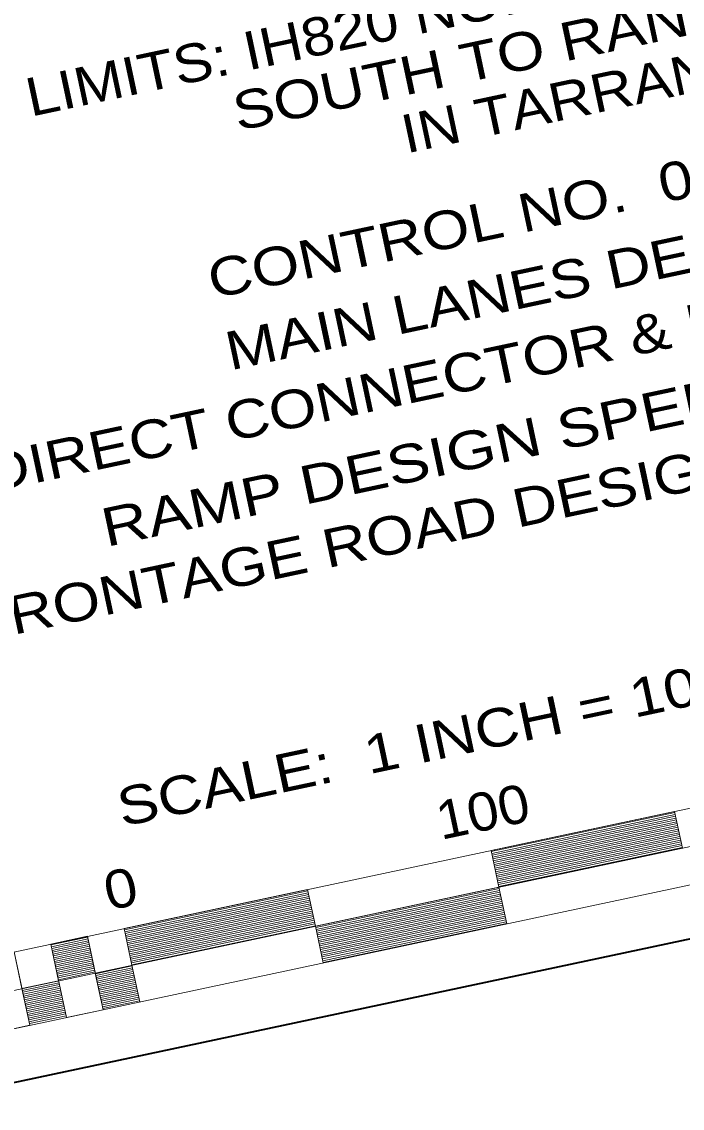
# Model space of a CAD drawing. Extents: x 2357218 to 2371708, y 6973728 to 6980157.
# Drawn here: x 2370630.2 to 2370806.3, y 6976807.8 to 6977097.4 of the extents above; entities that cross this region are included whole.
import ezdxf
from ezdxf.enums import TextEntityAlignment as Align

# ---------------------------------------------------------------- set-up
doc = ezdxf.new("R2010")
doc.units = 0
doc.header["$LTSCALE"] = 2
doc.layers.add('61', color=7, linetype='Continuous')
doc.layers.add('62', color=7, linetype='Continuous', lineweight=13)
doc.layers.add('63', color=7, linetype='Continuous', lineweight=13)

msp = doc.modelspace()

# ---------------------------------------------------------------- linework, layer by layer
at = {"layer": '62', "lineweight": 35}
msp.add_line((2371176.22, 6976931.098), (2370539.396, 6976795.736), dxfattribs=at)
at = {"layer": '62'}
for p, q in [((2370559.68, 6976834.897), (2370950.993, 6976918.073)), ((2370561.761, 6976825.114), (2370953.073, 6976908.29)), ((2370755.398, 6976876.2), (2370804.31, 6976886.597)), ((2370804.251, 6976886.882), (2370806.329, 6976877.099)), ((2370755.502, 6976875.711), (2370804.414, 6976886.108)), ((2370755.606, 6976875.221), (2370804.519, 6976885.619)), ((2370755.709, 6976874.731), (2370804.622, 6976885.129)), ((2370755.813, 6976874.243), (2370804.727, 6976884.64)), ((2370755.917, 6976873.754), (2370804.83, 6976884.151)), ((2370756.021, 6976873.265), (2370804.934, 6976883.661)), ((2370756.125, 6976872.777), (2370805.038, 6976883.173)), ((2370756.229, 6976872.286), (2370805.142, 6976882.683)), ((2370756.334, 6976871.797), (2370805.247, 6976882.194)), ((2370756.437, 6976871.309), (2370805.35, 6976881.705)), ((2370756.54, 6976870.82), (2370805.455, 6976881.216)), ((2370756.644, 6976870.331), (2370805.559, 6976880.727)), ((2370756.748, 6976869.841), (2370805.662, 6976880.238)), ((2370756.853, 6976869.352), (2370805.767, 6976879.749)), ((2370756.957, 6976868.864), (2370805.87, 6976879.26)), ((2370757.06, 6976868.374), (2370805.974, 6976878.77)), ((2370757.165, 6976867.885), (2370806.078, 6976878.281)), ((2370757.268, 6976867.395), (2370806.182, 6976877.792)), ((2370755.336, 6976876.485), (2370757.416, 6976866.702)), ((2370757.373, 6976866.907), (2370806.287, 6976877.303)), ((2370706.422, 6976866.088), (2370708.502, 6976856.304)), ((2370708.583, 6976855.926), (2370757.496, 6976866.323)), ((2370757.416, 6976866.702), (2370759.495, 6976856.919)), ((2370657.583, 6976855.338), (2370706.497, 6976865.736)), ((2370657.687, 6976854.85), (2370706.601, 6976865.247)), ((2370657.791, 6976854.359), (2370706.705, 6976864.756)), ((2370657.896, 6976853.871), (2370706.81, 6976864.267)), ((2370657.999, 6976853.382), (2370706.913, 6976863.778)), ((2370658.103, 6976852.892), (2370707.018, 6976863.288)), ((2370708.686, 6976855.438), (2370757.6, 6976865.834)), ((2370708.789, 6976854.948), (2370757.704, 6976865.344)), ((2370708.893, 6976854.46), (2370757.808, 6976864.856)), ((2370708.997, 6976853.97), (2370757.913, 6976864.367)), ((2370709.101, 6976853.481), (2370758.017, 6976863.877)), ((2370709.205, 6976852.993), (2370758.12, 6976863.39)), ((2370658.207, 6976852.403), (2370707.121, 6976862.8)), ((2370658.311, 6976851.915), (2370707.225, 6976862.31)), ((2370658.416, 6976851.425), (2370707.328, 6976861.822)), ((2370658.52, 6976850.936), (2370707.432, 6976861.333)), ((2370658.623, 6976850.447), (2370707.537, 6976860.843)), ((2370658.728, 6976849.958), (2370707.64, 6976860.354)), ((2370709.31, 6976852.503), (2370758.224, 6976862.9)), ((2370709.414, 6976852.014), (2370758.328, 6976862.412)), ((2370709.517, 6976851.524), (2370758.432, 6976861.923)), ((2370709.622, 6976851.035), (2370758.537, 6976861.433)), ((2370709.725, 6976850.547), (2370758.64, 6976860.944)), ((2370709.829, 6976850.057), (2370758.744, 6976860.454)), ((2370658.832, 6976849.469), (2370707.744, 6976859.864)), ((2370658.935, 6976848.979), (2370707.849, 6976859.377)), ((2370659.039, 6976848.49), (2370707.952, 6976858.887)), ((2370659.143, 6976848.001), (2370708.057, 6976858.397)), ((2370659.247, 6976847.512), (2370708.16, 6976857.909)), ((2370659.351, 6976847.023), (2370708.265, 6976857.421)), ((2370709.933, 6976849.567), (2370758.848, 6976859.965)), ((2370710.037, 6976849.078), (2370758.952, 6976859.476)), ((2370710.141, 6976848.589), (2370759.056, 6976858.986)), ((2370710.245, 6976848.1), (2370759.159, 6976858.498)), ((2370710.35, 6976847.61), (2370759.264, 6976858.008)), ((2370710.454, 6976847.122), (2370759.368, 6976857.519)), ((2370657.509, 6976855.691), (2370659.588, 6976845.908)), ((2370659.456, 6976846.534), (2370708.369, 6976856.931)), ((2370659.559, 6976846.045), (2370708.472, 6976856.443)), ((2370708.502, 6976856.304), (2370710.581, 6976846.522)), ((2370710.558, 6976846.633), (2370759.472, 6976857.03)), ((2370637.943, 6976851.531), (2370640.022, 6976841.749)), ((2370637.985, 6976851.338), (2370647.767, 6976853.419)), ((2370638.088, 6976850.849), (2370647.87, 6976852.929)), ((2370638.192, 6976850.358), (2370647.976, 6976852.439)), ((2370638.296, 6976849.87), (2370648.078, 6976851.95)), ((2370638.401, 6976849.381), (2370648.183, 6976851.461)), ((2370647.726, 6976853.612), (2370649.805, 6976843.829)), ((2370628.16, 6976849.453), (2370630.24, 6976839.67)), ((2370638.505, 6976848.891), (2370648.287, 6976850.971)), ((2370638.608, 6976848.403), (2370648.39, 6976850.482)), ((2370638.711, 6976847.914), (2370648.494, 6976849.993)), ((2370638.815, 6976847.426), (2370648.598, 6976849.505)), ((2370638.92, 6976846.937), (2370648.702, 6976849.015)), ((2370639.024, 6976846.447), (2370648.806, 6976848.526)), ((2370639.127, 6976845.958), (2370648.911, 6976848.036)), ((2370639.232, 6976845.468), (2370649.015, 6976847.548)), ((2370639.336, 6976844.979), (2370649.118, 6976847.057)), ((2370639.44, 6976844.491), (2370649.222, 6976846.569)), ((2370639.543, 6976844.001), (2370649.326, 6976846.08)), ((2370649.846, 6976843.635), (2370659.63, 6976845.714)), ((2370659.588, 6976845.909), (2370661.668, 6976836.125)), ((2370659.588, 6976845.908), (2370661.668, 6976836.126)), ((2370639.647, 6976843.513), (2370649.43, 6976845.59)), ((2370639.751, 6976843.023), (2370649.534, 6976845.102)), ((2370639.855, 6976842.534), (2370649.639, 6976844.613)), ((2370639.96, 6976842.045), (2370649.742, 6976844.124)), ((2370649.805, 6976843.83), (2370651.886, 6976834.047)), ((2370649.805, 6976843.828), (2370651.884, 6976834.046)), ((2370649.951, 6976843.146), (2370659.734, 6976845.224)), ((2370650.054, 6976842.657), (2370659.837, 6976844.737)), ((2370650.158, 6976842.168), (2370659.942, 6976844.248)), ((2370650.262, 6976841.678), (2370660.046, 6976843.758)), ((2370650.366, 6976841.189), (2370660.149, 6976843.27)), ((2370650.471, 6976840.7), (2370660.254, 6976842.78)), ((2370630.241, 6976839.659), (2370640.025, 6976841.739)), ((2370630.346, 6976839.17), (2370640.129, 6976841.249)), ((2370630.449, 6976838.681), (2370640.234, 6976840.761)), ((2370630.554, 6976838.192), (2370640.338, 6976840.271)), ((2370650.574, 6976840.211), (2370660.357, 6976842.291)), ((2370650.678, 6976839.722), (2370660.462, 6976841.802)), ((2370650.782, 6976839.232), (2370660.566, 6976841.313)), ((2370650.885, 6976838.744), (2370660.669, 6976840.824)), ((2370650.989, 6976838.255), (2370660.773, 6976840.334)), ((2370651.093, 6976837.766), (2370660.877, 6976839.846)), ((2370630.239, 6976839.671), (2370632.319, 6976829.887)), ((2370630.24, 6976839.671), (2370632.319, 6976829.888)), ((2370630.657, 6976837.702), (2370640.441, 6976839.782)), ((2370630.762, 6976837.214), (2370640.546, 6976839.293)), ((2370630.866, 6976836.725), (2370640.65, 6976838.804)), ((2370630.969, 6976836.235), (2370640.754, 6976838.315)), ((2370631.073, 6976835.746), (2370640.857, 6976837.826)), ((2370631.177, 6976835.257), (2370640.961, 6976837.337)), ((2370651.197, 6976837.277), (2370660.982, 6976839.357)), ((2370651.302, 6976836.786), (2370661.085, 6976838.866)), ((2370651.405, 6976836.298), (2370661.189, 6976838.378)), ((2370651.51, 6976835.809), (2370661.293, 6976837.888)), ((2370651.613, 6976835.32), (2370661.397, 6976837.399)), ((2370631.282, 6976834.768), (2370641.066, 6976836.848)), ((2370631.386, 6976834.279), (2370641.169, 6976836.358)), ((2370631.489, 6976833.79), (2370641.274, 6976835.87)), ((2370631.594, 6976833.301), (2370641.378, 6976835.38)), ((2370631.698, 6976832.811), (2370641.481, 6976834.89)), ((2370631.802, 6976832.322), (2370641.586, 6976834.401)), ((2370651.717, 6976834.831), (2370661.501, 6976836.911)), ((2370651.821, 6976834.341), (2370661.605, 6976836.421)), ((2370631.906, 6976831.834), (2370641.689, 6976833.912)), ((2370632.009, 6976831.344), (2370641.794, 6976833.423)), ((2370632.113, 6976830.855), (2370641.897, 6976832.934)), ((2370632.217, 6976830.365), (2370642.001, 6976832.445))]:
    msp.add_line(p, q, dxfattribs=at)
for points in [[(2370757.416, 6976866.702), (2370806.329, 6976877.099), (2370804.251, 6976886.882), (2370755.336, 6976876.485)], [(2370659.588, 6976845.908), (2370708.502, 6976856.304), (2370706.422, 6976866.088), (2370657.509, 6976855.691)], [(2370710.581, 6976846.522), (2370759.495, 6976856.919), (2370757.416, 6976866.702), (2370708.502, 6976856.304)], [(2370642.101, 6976831.966), (2370651.884, 6976834.046), (2370647.726, 6976853.612), (2370637.943, 6976851.531)], [(2370622.537, 6976827.807), (2370632.319, 6976829.887), (2370628.16, 6976849.453), (2370618.377, 6976847.373)]]:
    msp.add_lwpolyline(points, close=True, dxfattribs=at)
at = {"layer": '63'}
for p, q in [((2370559.68, 6976834.897), (2370950.993, 6976918.073)), ((2370561.761, 6976825.114), (2370953.073, 6976908.29)), ((2370563.839, 6976815.332), (2370955.152, 6976898.507)), ((2370755.398, 6976876.2), (2370804.31, 6976886.597)), ((2370804.251, 6976886.882), (2370806.329, 6976877.099)), ((2370755.502, 6976875.711), (2370804.414, 6976886.108)), ((2370755.606, 6976875.221), (2370804.519, 6976885.619)), ((2370755.709, 6976874.731), (2370804.622, 6976885.129)), ((2370755.813, 6976874.243), (2370804.727, 6976884.64)), ((2370755.917, 6976873.754), (2370804.83, 6976884.151)), ((2370756.021, 6976873.265), (2370804.934, 6976883.661)), ((2370756.125, 6976872.777), (2370805.038, 6976883.173)), ((2370756.229, 6976872.286), (2370805.142, 6976882.683)), ((2370756.334, 6976871.797), (2370805.247, 6976882.194)), ((2370756.437, 6976871.309), (2370805.35, 6976881.705)), ((2370756.54, 6976870.82), (2370805.455, 6976881.216)), ((2370756.644, 6976870.331), (2370805.559, 6976880.727)), ((2370756.748, 6976869.841), (2370805.662, 6976880.238)), ((2370756.853, 6976869.352), (2370805.767, 6976879.749)), ((2370756.957, 6976868.864), (2370805.87, 6976879.26)), ((2370757.06, 6976868.374), (2370805.974, 6976878.77)), ((2370757.165, 6976867.885), (2370806.078, 6976878.281)), ((2370757.268, 6976867.395), (2370806.182, 6976877.792)), ((2370755.336, 6976876.485), (2370757.416, 6976866.702)), ((2370757.373, 6976866.907), (2370806.287, 6976877.303)), ((2370706.422, 6976866.088), (2370708.502, 6976856.304)), ((2370708.583, 6976855.926), (2370757.496, 6976866.323)), ((2370757.416, 6976866.702), (2370759.495, 6976856.919)), ((2370657.583, 6976855.338), (2370706.497, 6976865.736)), ((2370657.687, 6976854.85), (2370706.601, 6976865.247)), ((2370657.791, 6976854.359), (2370706.705, 6976864.756)), ((2370657.896, 6976853.871), (2370706.81, 6976864.267)), ((2370657.999, 6976853.382), (2370706.913, 6976863.778)), ((2370658.103, 6976852.892), (2370707.018, 6976863.288)), ((2370708.686, 6976855.438), (2370757.6, 6976865.834)), ((2370708.789, 6976854.948), (2370757.704, 6976865.344)), ((2370708.893, 6976854.46), (2370757.808, 6976864.856)), ((2370708.997, 6976853.97), (2370757.913, 6976864.367)), ((2370709.101, 6976853.481), (2370758.017, 6976863.877)), ((2370709.205, 6976852.993), (2370758.12, 6976863.39)), ((2370658.207, 6976852.403), (2370707.121, 6976862.8)), ((2370658.311, 6976851.915), (2370707.225, 6976862.31)), ((2370658.416, 6976851.425), (2370707.328, 6976861.822)), ((2370658.52, 6976850.936), (2370707.432, 6976861.333)), ((2370658.623, 6976850.447), (2370707.537, 6976860.843)), ((2370658.728, 6976849.958), (2370707.64, 6976860.354)), ((2370709.31, 6976852.503), (2370758.224, 6976862.9)), ((2370709.414, 6976852.014), (2370758.328, 6976862.412)), ((2370709.517, 6976851.524), (2370758.432, 6976861.923)), ((2370709.622, 6976851.035), (2370758.537, 6976861.433)), ((2370709.725, 6976850.547), (2370758.64, 6976860.944)), ((2370709.829, 6976850.057), (2370758.744, 6976860.454)), ((2370658.832, 6976849.469), (2370707.744, 6976859.864)), ((2370658.935, 6976848.979), (2370707.849, 6976859.377)), ((2370659.039, 6976848.49), (2370707.952, 6976858.887)), ((2370659.143, 6976848.001), (2370708.057, 6976858.397)), ((2370659.247, 6976847.512), (2370708.16, 6976857.909)), ((2370659.351, 6976847.023), (2370708.265, 6976857.421)), ((2370709.933, 6976849.567), (2370758.848, 6976859.965)), ((2370710.037, 6976849.078), (2370758.952, 6976859.476)), ((2370710.141, 6976848.589), (2370759.056, 6976858.986)), ((2370710.245, 6976848.1), (2370759.159, 6976858.498)), ((2370710.35, 6976847.61), (2370759.264, 6976858.008)), ((2370710.454, 6976847.122), (2370759.368, 6976857.519)), ((2370657.509, 6976855.691), (2370659.588, 6976845.908)), ((2370659.456, 6976846.534), (2370708.369, 6976856.931)), ((2370659.559, 6976846.045), (2370708.472, 6976856.443)), ((2370708.502, 6976856.304), (2370710.581, 6976846.522)), ((2370710.558, 6976846.633), (2370759.472, 6976857.03)), ((2370637.943, 6976851.531), (2370640.022, 6976841.749)), ((2370637.985, 6976851.338), (2370647.767, 6976853.419)), ((2370638.088, 6976850.849), (2370647.87, 6976852.929)), ((2370638.192, 6976850.358), (2370647.976, 6976852.439)), ((2370638.296, 6976849.87), (2370648.078, 6976851.95)), ((2370638.401, 6976849.381), (2370648.183, 6976851.461)), ((2370647.726, 6976853.612), (2370649.805, 6976843.829)), ((2370628.16, 6976849.453), (2370630.24, 6976839.67)), ((2370638.505, 6976848.891), (2370648.287, 6976850.971)), ((2370638.608, 6976848.403), (2370648.39, 6976850.482)), ((2370638.711, 6976847.914), (2370648.494, 6976849.993)), ((2370638.815, 6976847.426), (2370648.598, 6976849.505)), ((2370638.92, 6976846.937), (2370648.702, 6976849.015)), ((2370639.024, 6976846.447), (2370648.806, 6976848.526)), ((2370639.127, 6976845.958), (2370648.911, 6976848.036)), ((2370639.232, 6976845.468), (2370649.015, 6976847.548)), ((2370639.336, 6976844.979), (2370649.118, 6976847.057)), ((2370639.44, 6976844.491), (2370649.222, 6976846.569)), ((2370639.543, 6976844.001), (2370649.326, 6976846.08)), ((2370649.846, 6976843.635), (2370659.63, 6976845.714)), ((2370659.588, 6976845.909), (2370661.668, 6976836.125)), ((2370659.588, 6976845.908), (2370661.668, 6976836.126)), ((2370639.647, 6976843.513), (2370649.43, 6976845.59)), ((2370639.751, 6976843.023), (2370649.534, 6976845.102)), ((2370639.855, 6976842.534), (2370649.639, 6976844.613)), ((2370639.96, 6976842.045), (2370649.742, 6976844.124)), ((2370649.805, 6976843.83), (2370651.886, 6976834.047)), ((2370649.805, 6976843.828), (2370651.884, 6976834.046)), ((2370649.951, 6976843.146), (2370659.734, 6976845.224)), ((2370650.054, 6976842.657), (2370659.837, 6976844.737)), ((2370650.158, 6976842.168), (2370659.942, 6976844.248)), ((2370650.262, 6976841.678), (2370660.046, 6976843.758)), ((2370650.366, 6976841.189), (2370660.149, 6976843.27)), ((2370650.471, 6976840.7), (2370660.254, 6976842.78)), ((2370630.241, 6976839.659), (2370640.025, 6976841.739)), ((2370630.346, 6976839.17), (2370640.129, 6976841.249)), ((2370630.449, 6976838.681), (2370640.234, 6976840.761)), ((2370630.554, 6976838.192), (2370640.338, 6976840.271)), ((2370650.574, 6976840.211), (2370660.357, 6976842.291)), ((2370650.678, 6976839.722), (2370660.462, 6976841.802)), ((2370650.782, 6976839.232), (2370660.566, 6976841.313)), ((2370650.885, 6976838.744), (2370660.669, 6976840.824)), ((2370650.989, 6976838.255), (2370660.773, 6976840.334)), ((2370651.093, 6976837.766), (2370660.877, 6976839.846)), ((2370630.239, 6976839.671), (2370632.319, 6976829.887)), ((2370630.24, 6976839.671), (2370632.319, 6976829.888)), ((2370630.657, 6976837.702), (2370640.441, 6976839.782)), ((2370630.762, 6976837.214), (2370640.546, 6976839.293)), ((2370630.866, 6976836.725), (2370640.65, 6976838.804)), ((2370630.969, 6976836.235), (2370640.754, 6976838.315)), ((2370631.073, 6976835.746), (2370640.857, 6976837.826)), ((2370631.177, 6976835.257), (2370640.961, 6976837.337)), ((2370651.197, 6976837.277), (2370660.982, 6976839.357)), ((2370651.302, 6976836.786), (2370661.085, 6976838.866)), ((2370651.405, 6976836.298), (2370661.189, 6976838.378)), ((2370651.51, 6976835.809), (2370661.293, 6976837.888)), ((2370651.613, 6976835.32), (2370661.397, 6976837.399)), ((2370631.282, 6976834.768), (2370641.066, 6976836.848)), ((2370631.386, 6976834.279), (2370641.169, 6976836.358)), ((2370631.489, 6976833.79), (2370641.274, 6976835.87)), ((2370631.594, 6976833.301), (2370641.378, 6976835.38)), ((2370631.698, 6976832.811), (2370641.481, 6976834.89)), ((2370631.802, 6976832.322), (2370641.586, 6976834.401)), ((2370651.717, 6976834.831), (2370661.501, 6976836.911)), ((2370651.821, 6976834.341), (2370661.605, 6976836.421)), ((2370631.906, 6976831.834), (2370641.689, 6976833.912)), ((2370632.009, 6976831.344), (2370641.794, 6976833.423)), ((2370632.113, 6976830.855), (2370641.897, 6976832.934)), ((2370632.217, 6976830.365), (2370642.001, 6976832.445))]:
    msp.add_line(p, q, dxfattribs=at)
for points in [[(2370757.416, 6976866.702), (2370806.329, 6976877.099), (2370804.251, 6976886.882), (2370755.336, 6976876.485)], [(2370659.588, 6976845.908), (2370708.502, 6976856.304), (2370706.422, 6976866.088), (2370657.509, 6976855.691)], [(2370710.581, 6976846.522), (2370759.495, 6976856.919), (2370757.416, 6976866.702), (2370708.502, 6976856.304)], [(2370642.101, 6976831.966), (2370651.884, 6976834.046), (2370647.726, 6976853.612), (2370637.943, 6976851.531)], [(2370622.537, 6976827.807), (2370632.319, 6976829.887), (2370628.16, 6976849.453), (2370618.377, 6976847.373)]]:
    msp.add_lwpolyline(points, close=True, dxfattribs=at)

# ---------------------------------------------------------------- texts
at = {"layer": '61'}
for s, width, p in [('LIMITS: IH820 NORTH INTERCHANGE AT SH121', 1.15, (2370806.917, 6977109.14)), ('SOUTH TO RANDOL MILL ROAD', 1.2, (2370810.078, 6977094.271)), ('IN TARRANT COUNTY', 1.15, (2370813.239, 6977079.404))]:
    msp.add_text(s, height=10.2, rotation=12, dxfattribs=dict(at, width=width)).set_placement(p, align=Align.CENTER)
at = {"layer": '62', "width": 1.2}
msp.add_text('CONTROL NO.  0008-13-123, 124, 138', height=10.2, rotation=12, dxfattribs=at).set_placement((2370681.072, 6977023.559))
at = {"layer": '62'}
for s, width, p in [('MAIN LANES DESIGN SPEED = 60 MPH', 1.2, (2370834.598, 6977036.084)), ('DIRECT CONNECTOR & RAMP DESIGN SPEED = 50 MPH', 1.2, (2370838.46, 6977017.911)), ('RAMP DESIGN SPEED VARIABLE 40 TO 50 MPH', 1.25, (2370842.737, 6976997.784)), ('FRONTAGE ROAD DESIGN SPEED VARIABLE 35 TO 40 MPH', 1.2, (2370847.295, 6976980.56)), ('SCALE:  1 INCH = 100 FT.', 1.2, (2370752.789, 6976903.182)), ('100', 1.1, (2370754.184, 6976881.893)), ('0', 1.15, (2370657.629, 6976861.375))]:
    msp.add_text(s, height=10.2, rotation=12, dxfattribs=dict(at, width=width)).set_placement(p, align=Align.CENTER)
at = {"layer": '63'}
for s, width, p in [('MAIN LANES DESIGN SPEED = 60 MPH', 1.2, (2370834.598, 6977036.084)), ('DIRECT CONNECTOR & RAMP DESIGN SPEED = 50 MPH', 1.2, (2370838.46, 6977017.911)), ('100', 1.1, (2370754.184, 6976881.893)), ('0', 1.15, (2370657.629, 6976861.375))]:
    msp.add_text(s, height=10.2, rotation=12, dxfattribs=dict(at, width=width)).set_placement(p, align=Align.CENTER)

doc.saveas('drawing.dxf')
